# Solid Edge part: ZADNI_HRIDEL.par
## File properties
Author: knedlova
Template: Iso Metric Part.par
Last saved by: Acer
Revision: 37
Application: Solid Edge
Username: Acer
Typ obsahu dokumentu: 0
Accuracy: 0,990
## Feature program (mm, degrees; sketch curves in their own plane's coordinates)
sketch for "unnamed RevolvedProtrusion 1" plane through (0, 0, 0) normal (0, -1, 0) x-axis (1, 0, 0)
  line (40.7, 0) -> (40.7, 8)
  line (40.7, 8) -> (-111.3, 8)
  line (-111.3, 8) -> (-111.3, 0)
  dimension (linear) = 111.3
revolve "unnamed RevolvedProtrusion 1" add full turn 360 deg about sketch line (-111.3, 0) -> (40.7, 0)
sketch for "unnamed RevolvedCutout 1" plane through (0, 0, 0) normal (0, -1, 0) x-axis (1, 0, 0)
  line (40.7, 8) -> (0, 8)
  line (0, 8) -> (0, 6)
  line (0, 6) -> (40.7, 6)
  line (40.7, 6) -> (40.7, 8)
revolve "unnamed RevolvedCutout 1" cut finite 360 deg
sketch for "unnamed RevolvedCutout 2" plane through (0, 0, 0) normal (0, -1, 0) x-axis (1, 0, 0)
  line (40.7, 6) -> (0.4, 6)
  line (0.4, 6) -> (0.4, 5)
  line (0.4, 5) -> (40.7, 5)
  line (40.7, 5) -> (40.7, 6)
revolve "unnamed RevolvedCutout 2" cut full turn 360 deg
sketch for "unnamed RevolvedCutout 3" plane through (0, 0, 0) normal (0, -1, 0) x-axis (1, 0, 0)
  line (40.7, 5) -> (23.9, 5)
  line (23.9, 5) -> (23.9, 4.8)
  line (23.9, 4.8) -> (40.7, 4.8)
  line (40.7, 4.8) -> (40.7, 5)
revolve "unnamed RevolvedCutout 3" cut full turn 360 deg
sketch for "unnamed RevolvedCutout 4" plane through (0, 0, 0) normal (0, -1, 0) x-axis (1, 0, 0)
  line (0, 0) -> (0, 0)
  line (-111.3, 8) -> (-57.6, 8)
  line (-57.6, 8) -> (-57.6, 6)
  line (-57.6, 6) -> (-111.3, 6)
  line (-111.3, 6) -> (-111.3, 8)
revolve "unnamed RevolvedCutout 4" cut full turn 360 deg
sketch for "unnamed RevolvedCutout 5" plane through (0, 0, 0) normal (0, -1, 0) x-axis (1, 0, 0)
  line (-111.3, 6) -> (-70.6, 6)
  line (-70.6, 6) -> (-70.6, 5)
  line (-70.6, 5) -> (-111.3, 5)
  line (-111.3, 5) -> (-111.3, 6)
revolve "unnamed RevolvedCutout 5" cut full turn 360 deg
slot "Slot_1"
chamfer "Chamfer_1" setback 0.5  SetBackValue2 = 45 deg
sketch for "ExtrudedCutout_2" #1 plane through (40.7, 0, 0) normal (1, 0, 0) x-axis (0, 1, 0)
  line (-2.6533, 4) -> (2.6533, 4)
sketch for "ExtrudedCutout_2" #2 plane through (40.7, 0, 0) normal (1, 0, 0) x-axis (0, 1, 0)
  line (-2.6533, -4) -> (2.6533, -4)
  arc centre (0, 0) radius 4.8 from (-2.6533, -4) to (2.6533, -4) ccw
extrude "ExtrudedCutout_2" cut finite 16 along -normal
sketch for "Hole_1" plane through (40.7, 0, 0) normal (1, 0, 0) x-axis (0, 1, 0)
  line (0, 0) -> (0, 0)
  hole centre (0, 0) bore radius 1.621
hole "Hole_1" nominal diameter 4 finite  VBottomAngle = 118 deg; ThreadDepth = 8 mm
mirror "unnamed Mirror 1" of "Hole_1", "ExtrudedCutout_2", "Chamfer_1", "unnamed RevolvedCutout 3" about plane through (-35.3, 0, 0) normal (1, 0, 0)
revolve "unnamed RevolvedCutout 6" cut full turn 360 deg
chamfer "unnamed Chamfer 1"
extrude "unnamed Cutout 1" cut finite 16
hole "unnamed Hole 1" finite
chamfer "Chamfer_3" setback 0.2  SetBackValue2 = 45 deg
chamfer "Chamfer_4" setback 0.5  SetBackValue2 = 45 deg
sketch for "unnamed RevolvedCutout 7" plane through (0, 0, 0) normal (0, -1, 0) x-axis (1, 0, 0)
revolve "unnamed RevolvedCutout 7" cut full turn 360 deg
sketch for "unnamed RevolvedCutout 8" plane through (0, 0, 0) normal (0, -1, 0) x-axis (1, 0, 0)
revolve "unnamed RevolvedCutout 8" cut full turn 360 deg
delete faces "unnamed DeleteFaces 1"
delete faces "unnamed DeleteFaces 2"
sketch for "unnamed RevolvedCutout 9" plane through (0, 0, 0) normal (0, -1, 0) x-axis (1, 0, 0)
  line (0, -5) -> (2, -5)
  line (2, -5) -> (2, -4.8)
  line (2, -4.8) -> (0, -4.8)
  line (0, -4.8) -> (0, -5)
revolve "unnamed RevolvedCutout 9" cut full turn 360 deg
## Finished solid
Body 1: solid body, 41 faces, 69 edges, 32 vertices.
  Faces by surface: plane 18, cylinder 14, cone 9
  Edges by curve: circle 35, line 24, intersection 10
Bounding box of the edges (mm): 152.000 x 16.000 x 16.000, from (-111.3, -8, -8) to (40.7, 8, 8).
Cylindrical faces by radius (mm): R1.621 x4, R2 x2, R4.8 x4, R5 x2, R6 x1, R8 x1
Conical faces (half-angle, radius in mm at the cone's reference point): 45 deg R4.3 x2, 45 deg R4.8 x3, 45 deg R5 x1, 45 deg R5.5 x1, 59 deg R1.621 x2
Planar faces by outward normal: +x 5, +z 3, -x 6, -y 1, -z 3
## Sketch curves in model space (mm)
line (-67.6, -6, 0) -> (-61.6, -6, 0)
line (0, 0, 0) -> (23.7, 0, 0)
line (2, 0, -5) -> (2, 0, -4.8)
line (2, 0, -4.8) -> (0, 0, -4.8)
line (0, 0, -4.8) -> (0, 0, -5)
line (0, 0, -5) -> (2, 0, -5)
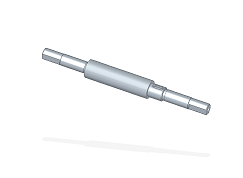
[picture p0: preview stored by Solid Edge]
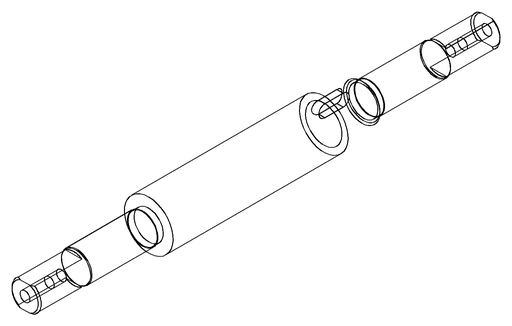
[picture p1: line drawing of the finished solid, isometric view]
